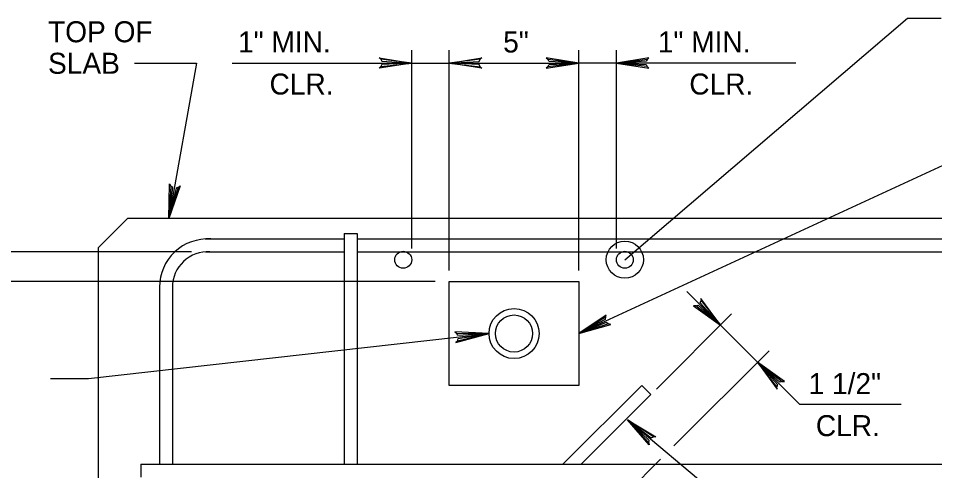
# Model space of a CAD drawing. Extents: x 641328 to 643024, y 298283 to 300065.
# Drawn here: x 642320.7 to 642451.6, y 299704.6 to 299769.2 of the extents above; entities that cross this region are included whole.
import ezdxf

# ---------------------------------------------------------------- set-up
doc = ezdxf.new("R2010")
doc.units = 0
for name, color, linetype in [('2', 7, 'Continuous'), ('63', 7, 'Continuous'), ('Default', 7, 'Continuous')]:
    doc.layers.add(name, color=color, linetype=linetype)

msp = doc.modelspace()

# ---------------------------------------------------------------- linework, layer by layer
at = {"layer": '2'}
for p, q in [((642407.35, 299734.74), (642447.71, 299769.2)), ((642447.71, 299769.2), (642452.53, 299769.2)), ((642376.92, 299736.36), (642376.92, 299764.65)), ((642382.27, 299733.19), (642382.27, 299764.65)), ((642400.79, 299733.19), (642400.79, 299764.65)), ((642406.14, 299736.36), (642406.14, 299764.65)), ((642346.2, 299762.78), (642342.26, 299740.64)), ((642459.62, 299751.39), (642400.79, 299724.2)), ((642461.47, 299740.64), (642336.36, 299740.64)), ((642367.26, 299738.47), (642367.26, 299705.55)), ((642367.26, 299738.47), (642369.11, 299738.47)), ((642369.11, 299738.47), (642369.11, 299705.55)), ((642347.41, 299737.7), (642367.26, 299737.7)), ((642369.11, 299737.7), (642461.47, 299737.7)), ((642345.46, 299735.85), (642310.15, 299735.85)), ((642332.17, 299736.44), (642332.17, 299611.94)), ((642347.47, 299735.85), (642367.26, 299735.85)), ((642369.11, 299735.85), (642461.47, 299735.85)), ((642380.29, 299731.61), (642310.15, 299731.61)), ((642340.89, 299730.82), (642340.89, 299705.55)), ((642342.74, 299730.82), (642342.74, 299705.55)), ((642330.76, 299717.79), (642387.96, 299724.2)), ((642325.35, 299717.79), (642330.76, 299717.79)), ((642409.77, 299716.8), (642398.52, 299705.55)), ((642409.77, 299716.8), (642411.07, 299715.49)), ((642411.07, 299715.49), (642401.14, 299705.55)), ((642445.29, 299680.52), (642407.72, 299711.86)), ((642338.24, 299705.55), (642461.61, 299705.55)), ((642338.24, 299705.55), (642338.24, 299703.7))]:
    msp.add_line(p, q, dxfattribs=at)
for points in [[(642343.64, 299745.08), (642343.28, 299744.97), (642342.26, 299740.64), (642343.64, 299745.08), (642343.88, 299745.28), (642342.26, 299740.64), (642342.82, 299745.05), (642342.52, 299745.26), (642342.26, 299740.64), (642342.35, 299745.55), (642342.52, 299745.26)], [(642383.44, 299723.13), (642383.57, 299723.48), (642387.96, 299724.2), (642383.44, 299723.13), (642383.22, 299722.9), (642387.96, 299724.2), (642383.52, 299723.94), (642383.33, 299724.25), (642387.96, 299724.2), (642383.06, 299724.45), (642383.33, 299724.25)]]:
    msp.add_lwpolyline(points, dxfattribs=at)
msp.add_lwpolyline([(642382.27, 299731.61), (642400.79, 299731.61), (642400.79, 299716.8), (642382.27, 299716.8)], close=True, dxfattribs=at)
for centre in [(642375.71, 299734.74), (642407.35, 299734.74)]:
    msp.add_circle(centre, 1.21, dxfattribs=at)
for radius in [6.89, 5.04]:
    msp.add_arc((642347.79, 299730.82), radius, 86.4281, 180, dxfattribs=at)
at = {"layer": '63'}
for p, q in [((642351.28, 299762.82), (642382.27, 299762.82)), ((642382.27, 299762.82), (642400.79, 299762.82)), ((642431.79, 299762.82), (642400.79, 299762.82)), ((642420.99, 299725.41), (642416.21, 299730.19)), ((642411.87, 299716.28), (642422.59, 299727)), ((642432.35, 299714.05), (642420.99, 299725.41)), ((642414.35, 299708.16), (642427.94, 299721.75)), ((642446.82, 299714.05), (642432.35, 299714.05)), ((642403.53, 299697.33), (642412.44, 299706.25))]:
    msp.add_line(p, q, dxfattribs=at)
for points in [[(642372.49, 299763.38), (642372.66, 299763.06), (642376.92, 299762.82), (642372.49, 299763.38), (642372.27, 299763.57), (642376.92, 299762.82), (642372.66, 299762.61), (642372.51, 299762.3), (642376.92, 299762.82), (642372.27, 299762.08), (642372.51, 299762.3)], [(642386.7, 299762.27), (642386.54, 299762.59), (642382.27, 299762.82), (642386.7, 299762.27), (642386.93, 299762.07), (642382.27, 299762.82), (642386.53, 299763.04), (642386.69, 299763.35), (642382.27, 299762.82), (642386.93, 299763.56), (642386.69, 299763.35)], [(642396.36, 299762.27), (642396.53, 299762.59), (642400.79, 299762.82), (642396.36, 299762.27), (642396.14, 299762.07), (642400.79, 299762.82), (642396.53, 299763.04), (642396.38, 299763.35), (642400.79, 299762.82), (642396.14, 299763.56), (642396.38, 299763.35)], [(642410.57, 299763.38), (642410.41, 299763.06), (642406.14, 299762.82), (642410.57, 299763.38), (642410.8, 299763.57), (642406.14, 299762.82), (642410.4, 299762.61), (642410.56, 299762.3), (642406.14, 299762.82), (642410.8, 299762.08), (642410.56, 299762.3)], [(642417.47, 299728.14), (642417.81, 299728.26), (642420.99, 299725.41), (642417.47, 299728.14), (642417.17, 299728.17), (642420.99, 299725.41), (642418.13, 299728.57), (642418.24, 299728.9), (642420.99, 299725.41), (642418.22, 299729.22), (642418.24, 299728.9)], [(642404.57, 299726.57), (642404.56, 299726.21), (642400.79, 299724.2), (642404.57, 299726.57), (642404.7, 299726.84), (642400.79, 299724.2), (642404.74, 299725.8), (642405.02, 299725.58), (642400.79, 299724.2), (642405.33, 299725.49), (642405.02, 299725.58)], [(642429.83, 299717.36), (642429.49, 299717.25), (642426.31, 299720.09), (642429.83, 299717.36), (642430.13, 299717.33), (642426.31, 299720.09), (642429.17, 299716.93), (642429.06, 299716.6), (642426.31, 299720.09), (642429.08, 299716.28), (642429.06, 299716.6)], [(642410.77, 299708.6), (642410.84, 299708.95), (642407.72, 299711.86), (642410.77, 299708.6), (642410.82, 299708.3), (642407.72, 299711.86), (642411.13, 299709.29), (642411.45, 299709.44), (642407.72, 299711.86), (642411.77, 299709.44), (642411.45, 299709.44)]]:
    msp.add_lwpolyline(points, dxfattribs=at)
for centre, radius in [((642407.35, 299734.74), 2.65), ((642391.53, 299724.2), 3.57), ((642391.53, 299724.2), 2.65)]:
    msp.add_circle(centre, radius, dxfattribs=at)
at = {"layer": 'Default'}
for p, q in [((642337.36, 299762.78), (642346.2, 299762.78)), ((642332.17, 299736.44), (642336.36, 299740.64))]:
    msp.add_line(p, q, dxfattribs=at)

# ---------------------------------------------------------------- texts
at = {"layer": '2'}
for s, p in [('TOP OF', (642324.99, 299765.78)), ('SLAB', (642324.99, 299761.28))]:
    msp.add_text(s, height=3, dxfattribs=at).set_placement(p)
at = {"layer": '63'}
for s, p in [('1" MIN. ', (642352.12, 299764.32)), ('5"', (642389.98, 299764.32)), ('1" MIN. ', (642412.06, 299764.32)), ('CLR.', (642356.62, 299758.32)), ('CLR.', (642416.56, 299758.32))]:
    msp.add_text(s, height=3, dxfattribs=at).set_placement(p)
for s, p in [('1 1/2"', (642433.59, 299715.55)), ('CLR.', (642434.63, 299709.55))]:
    msp.add_text(s, height=3, rotation=360, dxfattribs=at).set_placement(p)

doc.saveas('drawing.dxf')
